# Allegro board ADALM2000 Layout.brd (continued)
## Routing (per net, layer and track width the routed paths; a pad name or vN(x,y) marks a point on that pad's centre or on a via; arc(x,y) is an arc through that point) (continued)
UNNAMED_30_AD9963_I47_TRXD4: length 32.5
  TOP w0.102: v2(63.09,41.09) U2.28
  L6_SIG w0.114: v2(89.63,37.28) 87.22,37.28 86.71,37.79 86.21,37.79 85.82,38.17 85.82,39.95 84.68,41.09 70.33,41.09 68.93,42.49 67.79,42.49 67.03,41.73 63.72,41.73 v2(63.09,41.09)
  BOTTOM w0.102: v2(89.63,37.28) 89.63,37.67 89.32,37.98 R184.1
UNNAMED_30_AD9963_I47_TRXD5: length 36.4
  TOP w0.102: U2.27 62.58,41.96 62.58,40.46 v2(62.08,39.95)
  L6_SIG w0.114: v2(62.08,39.95) 62.08,38.55 61.89,38.36 61.89,37.86 62.2,37.54 63.22,37.54 63.54,37.86 63.54,40.14 64.11,40.71 66.77,40.71 67.79,39.7 68.55,39.7 69.19,40.33 83.41,40.33 84.81,38.94 84.81,38.3 85.7,37.41 86.59,37.41 87.48,36.52 v2(87.86,36.52)
  BOTTOM w0.102: R183.1 v2(87.86,36.52)
UNNAMED_30_AD9963_I47_TRXD6: length 34.3
  TOP w0.102: U2.26 62.09,40.73 v2(62.08,40.71)
  L6_SIG w0.114: v2(62.08,40.71) 62.58,40.21 62.58,39.06 62.71,38.94 63.09,38.94 63.22,39.06 63.22,40.33 62.58,40.97 62.58,41.48 63.09,41.98 66.9,41.98 67.66,42.75 69.06,42.75 70.33,41.48 84.81,41.48 86.71,39.57 86.71,38.94 v2(86.33,38.55)
  BOTTOM w0.102: R182.1 v2(86.33,38.55)
UNNAMED_30_AD9963_I47_TRXD7: length 33.7
  TOP w0.102: v2(61.59,41.22) U2.25
  L6_SIG w0.114: v2(84.3,38.55) 83.79,39.06 83.79,39.44 83.28,39.95 69.44,39.95 68.81,39.32 67.66,39.32 66.65,40.33 64.23,40.33 63.85,39.95 63.85,37.54 63.47,37.16 61.19,37.16 60.55,37.79 60.55,38.11 60.74,38.3 61.31,38.3 61.59,38.57 v2(61.59,41.22)
  BOTTOM w0.102: v2(84.3,38.55) R181.1
UNNAMED_30_AD9963_I47_TRXD8: length 37.7
  TOP w0.102: v2(61.09,40.71) U2.24
  L6_SIG w0.114: v2(61.09,40.71) 61.09,41.5 61.82,42.24 66.77,42.24 67.54,43 70.08,43 71.22,41.86 84.94,41.86 86.98,39.82 86.98,38.16 87.48,37.67 89,37.67 89.13,37.79 89.89,37.79 90.9,36.78 90.9,36.48 v2(91.44,35.95)
  BOTTOM w0.102: R180.1 v2(91.44,35.95)
UNNAMED_30_AD9963_I47_TRXD9: length 36.9
  TOP w0.102: v2(60.59,41.22) U2.23
  L6_SIG w0.114: v2(60.59,41.22) 60.59,41.89 61.19,42.49 66.65,42.49 67.41,43.25 70.2,43.25 71.22,42.24 85.06,42.24 87.35,39.95 87.35,38.3 87.6,38.05 88.87,38.05 89,38.17 90.02,38.17 90.27,37.92 90.78,37.92 v2(91.41,38.55)
  BOTTOM w0.102: R179.1 v2(91.41,38.55)
UNNAMED_30_AD9963_I47_TRXD10: length 34.3
  TOP w0.102: v2(60.09,40.71) U2.22
  L6_SIG w0.114: v2(60.09,40.71) 60.09,41.9 60.93,42.75 66.52,42.75 67.28,43.51 72.49,43.51 73.38,42.62 85.19,42.62 87.86,39.95 v2(87.86,38.55)
  BOTTOM w0.102: R178.1 v2(87.86,38.55)
UNNAMED_30_AD9963_I47_TRXD11: length 35.9
  TOP w0.102: v2(59.59,41.22) U2.21
  L6_SIG w0.114: v2(90.4,38.55) 89.76,38.55 85.32,43 77.57,43 76.93,43.63 73.51,43.63 73.25,43.89 67.28,43.89 66.39,43 60.55,43 59.59,42.04 v2(59.59,41.22)
  BOTTOM w0.102: R177.1 v2(90.4,38.55)
UNNAMED_30_AD9963_I47_TRXIQ: length 34.3
  TOP w0.102: v2(66.59,39.82) 66.59,39.38 66.77,39.19 67.06,39.19 67.2,39.33 67.2,39.68 67.34,39.82 67.54,39.82 67.68,39.68 67.68,39.33 67.83,39.19 68.05,39.19 68.19,39.33 68.19,39.68 68.34,39.82 68.54,39.82 68.68,39.68 68.68,39.33 68.82,39.19 69.44,39.19 69.57,39.06 69.57,38.81 69.44,38.68 66.39,38.68 66.14,38.94 66.14,40.21 66.59,40.65 U2.35
  L6_SIG w0.114: v2(66.59,39.82) 67.48,38.94 68.93,38.94 69.57,39.57 80.57,39.57 80.71,39.43 80.71,39.21 80.86,39.06 81.06,39.06 81.21,39.21 81.21,39.43 81.35,39.57 81.56,39.57 81.7,39.43 81.7,39.21 81.85,39.06 82.05,39.06 82.2,39.21 82.2,39.43 82.34,39.57 83.03,39.57 83.27,39.33 83.27,39.04 83.16,38.94 82.65,38.94 82.27,38.55 v2(81.38,38.55)
  BOTTOM w0.102: v2(81.38,38.55) 81.38,38.24 R176.1
UNNAMED_30_AD9963_I47_TXCLK: length 3.8
  TOP w0.102: U2.37 67.85,42.56 68.76,41.65 70.28,41.65 R174.1
UNNAMED_30_AD9963_I47_TXD0: length 1.6
  TOP w0.102: U2.50 68.27,49.06 68.74,48.59 69.06,48.59
UNNAMED_30_AD9963_I47_TXD1: length 3.5
  TOP w0.102: R172.2 70.46,48.4 70.2,48.14 68.68,48.14 68.26,48.56 U2.49
UNNAMED_30_AD9963_I47_TXD2: length 1.5
  TOP w0.102: U2.48 68.26,48.06 68.62,47.7 69.06,47.7
UNNAMED_30_AD9963_I47_TXD3: length 3.4
  TOP w0.102: U2.47 68.25,47.56 68.62,47.19 70.84,47.19 R169.2
UNNAMED_30_AD9963_I47_TXD4: length 1.5
  TOP w0.102: 69.06,46.68 68.68,46.68 68.3,47.06 U2.46
UNNAMED_30_AD9963_I47_TXD5: length 3.4
  TOP w0.102: U2.45 67.69,46.56 68.3,46.56 68.74,46.11 R167.2
UNNAMED_30_AD9963_I47_TXD6: length 1.6
  TOP w0.102: 69.06,45.54 68.87,45.73 68.62,45.73 68.29,46.06 U2.44
UNNAMED_30_AD9963_I47_TXD7: length 3.5
  TOP w0.102: U2.43 68.22,45.56 68.81,44.97 R113.2
UNNAMED_30_AD9963_I47_TXD8: length 1.7
  TOP w0.102: U2.42 68.27,45.06 68.74,44.59 68.87,44.59 69.06,44.4
UNNAMED_30_AD9963_I47_TXD9: length 3.6
  TOP w0.102: U2.41 68.33,44.56 68.62,44.27 68.62,44.08 68.87,43.83 R109.2
UNNAMED_30_AD9963_I47_TXD10: length 1.7
  TOP w0.102: U2.40 68.25,44.06 69.06,43.25
UNNAMED_30_AD9963_I47_TXD11: length 4.1
  TOP w0.102: R110.2 70.33,42.68 68.74,42.68 68.62,42.81 68.62,43.25 68.31,43.56 U2.39
UNNAMED_30_AD9963_I47_TXIQ: length 2.1
  TOP w0.102: 69.06,42.11 68.68,42.11 68.36,42.43 68.36,42.94 68.24,43.06 U2.38
UNNAMED_30_CAP_I112_N1: length 1
  TOP w0.102: C66.1 70.01,53.48 69.82,53.29
UNNAMED_31_AD8066_I6_INV: length 2.8
  TOP w0.102: C89.1 34.31,50.37 R24.1 34.52,51.46 A3.2
UNNAMED_31_AD8066_I6_NINV: length 8.7
  TOP w0.102: C85.2 31.78,55.06 R22.2 32.08,55.37 36.35,55.37 36.57,55.14 36.57,54.76 36.4,54.58 35.96,54.58 35.79,54.4 A3.3
UNNAMED_31_AD8066_I6_OUT: length 17.2
  TOP w0.102: R26.1 38.79,57.88 38.28,57.88 v2(38.07,58.09) ; C89.2 33.45,50.37 R24.2 33.25,51.46 A3.1 33.25,54.43 33.5,54.68 v2(33.88,54.68)
  BOTTOM w0.102: v2(33.88,54.68) 34.29,55.09 34.29,55.34 34.09,55.55 33.69,55.55 33.04,54.9 33.04,54.12 33.37,53.79 34.64,53.79 35.91,55.06 35.91,56.72 37.08,57.88 37.87,57.88 v2(38.07,58.09)
UNNAMED_31_AD8066_I55_INV: length 2.9
  TOP w0.102: A3.6 35.79,59.81 R25.1 35.59,60.03 C92.1
UNNAMED_31_AD8066_I55_NINV: length 8.7
  TOP w0.102: C88.2 31.77,57.09 R23.2 32.15,55.7 36.8,55.7 37.06,55.95 A3.5
UNNAMED_31_AD8066_I55_OUT: length 17.3
  TOP w0.102: v2(38.07,57.38) 38.25,57.55 38.81,57.55 R27.1 ; v2(33.88,56.21) 34.52,56.84 A3.7 34.52,59.81 R25.2 34.71,60.03 C92.2
  BOTTOM w0.102: v2(38.07,57.38) 37.9,57.55 37.22,57.55 36.24,56.58 36.24,54.93 34.78,53.46 33.24,53.46 32.71,53.99 32.71,55.04 v2(33.88,56.21)
UNNAMED_31_ADA49402V2_I232_: length 4.7
  TOP w0.203: U3.23 44.05,58.1 v1(43.79,58.37)
  BOTTOM w0.102: R34.2 43.1,59.05 v1(43.79,58.37)
  BOTTOM w0.114: C103.2 41.17,59.36 42.08,59.36 R34.2
UNNAMED_31_ADA49402V2_I232__1: length 6.1
  TOP w0.102: R27.2 40.26,57.58 40.56,57.58 R28.2 41.15,57.55 41.43,57.55 v2(41.63,57.35) 41.86,57.58 42.28,57.58 42.95,56.91 42.95,56.54 42.85,56.44 U3.1
  BOTTOM w0.114: C104.1 42.19,57.35 v2(41.63,57.35) 41.07,57.35 R35.1
UNNAMED_31_ADA49402V2_I232__2: length 2.9
  TOP w0.203: v1(41.68,55.94) U3.2
  BOTTOM w0.114: C104.2 42.06,55.94 v1(41.68,55.94) 41.21,55.94 R35.2
UNNAMED_31_ADA49402V2_I232__3: length 6
  TOP w0.102: U3.24 43.14,57.19 42.42,57.91 41.83,57.91 v2(41.63,58.11) 41.4,57.88 41.17,57.88 R29.2 40.59,57.91 40.23,57.91 R26.2
  BOTTOM w0.114: C103.1 40.94,58.11 v2(41.63,58.11) 42.31,58.11 R34.1
UNNAMED_31_ADA49402V2_I232__4: length 7.7
  TOP w0.102: U3.19 46.47,57.19 46.86,57.58 49.2,57.58 52.31,54.46
UNNAMED_31_ADA49402V2_I232__5: length 7.7
  TOP w0.102: U3.18 46.73,56.44 46.58,56.59 46.58,56.83 47,57.25 49.06,57.25 51.61,54.7 51.61,54.23 51.69,54.15 R38.1
UNNAMED_31_ADA49402V2_I232_VOCM: length 9.3
  TOP w0.203: U3.17 47.59,55.94 v1(47.85,56.21) ; v1(45.82,51.51) 45.82,52.02 45.55,52.28 U3.11
  BOTTOM w0.203: R36.1 47.85,56.92 v1(47.85,56.21) 46.33,54.68 46.33,53.92 45.82,53.41 v1(45.82,51.51)
UNNAMED_31_ADA49402V2_I233_: length 1.9
  TOP w0.203: U3.8 44.05,52.41 v1(43.91,52.27)
  BOTTOM w0.203: v1(43.91,52.27) 44.22,51.97 R33.2
UNNAMED_31_ADA49402V2_I233__1: length 7
  TOP w0.203: v1(47.72,53.29) 47.7,53.31 46.94,53.31 46.8,53.45 U3.13
  BOTTOM w0.203: R39.1 50.9,55.5 50.57,55.83 49.12,55.83 48.23,54.94 48.23,53.79 v1(47.72,53.29)
UNNAMED_31_ADA49402V2_I233__2: length 7.8
  TOP w0.203: U3.12 46.05,52.54 46.2,52.4 46.45,52.4 v1(46.71,52.65)
  BOTTOM w0.203: R40.1 50.6,55.09 50.37,55.32 49.25,55.32 48.74,54.81 48.74,53.29 48.11,52.65 v1(46.71,52.65)
UNNAMED_31_ADA49402V2_I233__3: length 1.8
  TOP w0.203: v1(41.88,54.3) 42.02,54.44 U3.5
  BOTTOM w0.102: R32.2 41.17,54.3 v1(41.88,54.3)
UNNAMED_31_ADA49402V2_I233__4: length 2.8
  TOP w0.203: U3.7 43.55,52.67 v1(43.15,52.27)
  BOTTOM w0.102: R31.2 R33.1
  BOTTOM w0.203: v1(43.15,52.27) 43.15,51.71 R33.1
UNNAMED_31_ADA49402V2_I233__5: length 2.7
  TOP w0.203: v1(41.88,53.54) 42.28,53.94 U3.6
  BOTTOM w0.102: R30.2 42.6,53.54 v1(41.88,53.54) 41.17,53.54 R32.1
UNNAMED_31_ADG202N_I1_D: length 17.7
  TOP w0.102: A4.15 25.91,59.51 26.03,59.64 29.03,59.64 29.16,59.51 A4.10 29.16,57.02 28.9,56.77 28.9,55.98 29.16,55.73 29.87,55.73 v2(30.07,55.93) 30.25,55.75 30.58,55.75 R23.1 30.91,57.09 C88.1
  BOTTOM w0.102: A2.6 30.16,53.53 30.02,53.67 29.63,53.67 29.45,53.85 29.45,54.04 29.59,54.18 30.79,54.18 31.23,54.61 31.23,55.52 30.82,55.93 v2(30.07,55.93)
UNNAMED_31_ADG202N_I1_S: length 13.7
  TOP w0.203: A4.14 26.56,57.39 26.39,57.22 24.99,57.22 24.74,57.48 24.74,58.37 v1(24.23,58.87)
  BOTTOM w0.102: C185.1 C181.2 21.57,57.35 20.93,57.35 20.51,56.93 R17.2 19.12,56.93 C73.2 ; C185.1 22.54,57.89 R18.1 22.54,60.3 C74.1 ; C185.1 23.09,57.86 23.21,57.86 v1(24.23,58.87)
UNNAMED_31_ADG202N_I2_S: length 17.7
  TOP w0.102: C72.2 19.72,56.72 R16.2 20.71,55.73 21.33,55.73 v2(21.56,55.95) 22.11,55.95 C69.1 23.51,55.75 28.01,55.75 28.24,55.98 28.24,57.11 28.51,57.37 A4.11
  BOTTOM w0.102: v2(21.56,55.95) 21.82,56.21 C181.1 21.68,56.46 21.31,56.46 20.58,55.73 R17.1 19.12,55.73 C73.1
UNNAMED_31_ADG202N_I19_D: length 17.6
  TOP w0.102: A4.2 25.91,51.64 26.01,51.53 29.06,51.53 29.16,51.64 A4.7 29.16,53.8 28.9,54.05 28.9,55.12 29.18,55.39 29.89,55.39 v2(30.07,55.22) 30.27,55.42 30.56,55.42 R22.1 30.9,55.06 C85.1
  BOTTOM w0.102: v2(30.07,55.22) 30.26,55.41 30.26,55.53 30.33,55.6 30.68,55.6 30.9,55.38 30.9,54.75 30.66,54.51 29.45,54.51 29.12,54.18 29.12,53.78 29.01,53.67 28.34,53.67 28.21,53.53 A2.3
UNNAMED_31_ADG202N_I19_S: length 17.6
  TOP w0.102: C75.2 19.72,54.43 R19.2 20.69,55.39 21.36,55.39 v2(21.56,55.19) 22.11,55.19 C71.1 23.53,55.42 27.3,55.42 27.66,55.06 27.66,54.68 27.4,54.43 26.9,54.43 26.56,54.09 A4.3
  BOTTOM w0.102: C76.1 20.32,54.37 R20.1 20.64,54.05 21.25,54.05 21.75,54.55 C189.1 21.56,54.8 v2(21.56,55.19)
UNNAMED_31_ADG202N_I20_S: length 16.4
  TOP w0.203: v1(28.17,54.94) 28.51,54.6 A4.6
  BOTTOM w0.102: C77.1 23.4,52.05 R21.1 23.31,53.08 C336.1 ; C336.1 C189.2 21.06,53.55 20.58,53.07 R20.2 19.12,53.07 C76.2 ; C336.1 22.84,53.55 23.47,54.18 23.47,54.94 24.1,55.57 27.53,55.57 v1(28.17,54.94)
UNNAMED_31_ADG1404V2_I235_D: length 12
  BOTTOM w0.102: A2.2 27.56,50.97 28.04,50.49 31.98,50.49 32.61,51.13 34.14,51.13 35.28,52.27 36.17,52.27 36.35,52.09 U8.6
UNNAMED_31_DIO3PV3_I80_N: length 4.8
  BOTTOM w0.203: R40.2 51.2,54.05 D21.2 52.48,52.77 52.67,52.77 54.07,54.18 54.07,54.41 D20.2
UNNAMED_31_DIO3PV3_I80_P: length 6.2
  L5_SIG w0.114: v1(50.74,52.99) 50.74,53.63 v1(52.55,55.45)
  BOTTOM w0.203: D21.1 51.27,52.46 v1(50.74,52.99) ; D20.1 52.77,54.08 R39.2 51.99,54.89 v1(52.55,55.45)
UNNAMED_32_AD8066_I42_INV: length 2.9
  TOP w0.102: A5.6 35.79,47.87 R50.1 35.59,48.09 C146.1
UNNAMED_32_AD8066_I42_NINV: length 8.7
  TOP w0.102: A5.5 37.06,44.02 36.78,43.74 32.18,43.74 R48.2 31.77,45.15 C143.2
UNNAMED_32_AD8066_I42_OUT: length 16.9
  TOP w0.102: v2(38.34,45.44) 38.54,45.64 38.79,45.64 R53.1 ; C146.2 34.71,48.09 R50.2 34.52,47.87 A5.7 34.52,44.9 v2(33.88,44.27)
  BOTTOM w0.102: v2(33.88,44.27) 33.48,43.87 32.71,43.1 32.71,42.05 33.24,41.53 34.78,41.53 37.56,44.31 37.56,45.29 37.89,45.62 38.16,45.62 v2(38.34,45.44)
UNNAMED_32_AD8066_I82_INV: length 2.9
  TOP w0.102: C147.1 34.31,38.31 R51.1 34.52,39.39 34.52,41.09
UNNAMED_32_AD8066_I82_NINV: length 8.8
  TOP w0.102: C145.2 31.78,43.12 R49.2 32.05,43.41 36.37,43.41 36.65,43.13 36.65,42.9 36.4,42.64 35.96,42.64 35.79,42.47 35.79,41.09
UNNAMED_32_AD8066_I82_OUT: length 16.9
  TOP w0.102: v2(33.88,42.75) 33.45,42.75 33.25,42.54 33.25,39.39 R51.2 33.45,38.31 C147.2 ; v2(38.34,46.15) 38.52,45.97 38.81,45.97 R52.1
  BOTTOM w0.102: v2(38.34,46.15) 38.14,45.95 37.76,45.95 37.23,45.42 37.23,44.45 34.64,41.86 33.37,41.86 33.04,42.19 33.04,42.96 33.62,43.54 33.71,43.63 34.01,43.63 34.21,43.43 34.21,43.08 v2(33.88,42.75)
UNNAMED_32_ADA49402V2_I190_: length 3
  TOP w0.203: v2(41.63,44.01) 41.63,44 U4.2
  BOTTOM w0.114: C163.2 42.06,44.01 v2(41.63,44.01) 41.21,44.01 R61.2
UNNAMED_32_ADA49402V2_I190__1: length 6
  TOP w0.102: R52.2 40.26,45.95 40.56,45.95 R55.2 41.17,45.95 41.43,45.95 v2(41.63,46.15) 41.83,45.95 42.48,45.95 43.17,45.25 U4.24
  BOTTOM w0.114: C162.1 40.94,46.17 41.58,46.17 41.6,46.15 v2(41.63,46.15) 41.65,46.15 41.68,46.17 42.31,46.17 R60.1
UNNAMED_32_ADA49402V2_I190__2: length 6
  TOP w0.102: U4.1 42.95,44.65 42.95,45.01 42.34,45.62 41.81,45.62 v2(41.63,45.44) 41.45,45.62 41.15,45.62 R54.2 40.59,45.62 40.23,45.62 R53.2
  BOTTOM w0.114: R61.1 41.07,45.41 41.6,45.41 v2(41.63,45.44) 41.65,45.41 42.19,45.41 C163.1
UNNAMED_32_ADA49402V2_I190__3: length 4.9
  TOP w0.203: U4.23 44.05,46.04 43.79,46.3 43.41,46.3 43.15,46.56 v1(43.15,47.06)
  BOTTOM w0.102: R60.2 42.47,47.11 42.52,47.06 v1(43.15,47.06)
  BOTTOM w0.114: R60.2 42.11,47.39 41.14,47.39 C162.2
UNNAMED_32_ADA49402V2_I190__4: length 3.6
  TOP w0.102: R63.1 49.15,45.87 49.03,45.87 47.05,45.87 46.44,45.25 U4.19
UNNAMED_32_ADA49402V2_I190__5: length 3.6
  TOP w0.102: R64.1 49.27,45.16 48.89,45.54 47.19,45.54 46.68,45.03 46.68,44.62 U4.18
UNNAMED_32_ADA49402V2_I190_VOCM: length 9.8
  TOP w0.203: v1(45.69,40.33) 45.55,40.47 U4.11 ; U4.17 47.46,44 v1(47.72,44.27)
  L5_SIG w0.114: v1(47.72,44.27) 47.72,41.22 47.98,40.97 47.98,40.08 47.6,39.7 46.33,39.7 v1(45.69,40.33)
  BOTTOM w0.102: R62.1 47.72,43.59 v1(47.72,44.27)
UNNAMED_32_ADA49402V2_I191_: length 1.8
  TOP w0.203: U4.8 44.05,40.47 v1(43.91,40.33)
  BOTTOM w0.203: R59.2 43.91,39.62 v1(43.91,40.33)
UNNAMED_32_ADA49402V2_I191__1: length 7.4
  TOP w0.203: v1(46.45,40.33) 46.05,40.73 U4.12
  BOTTOM w0.203: R66.1 47.72,45.1 47.22,44.59 47.22,41.09 v1(46.45,40.33)
UNNAMED_32_ADA49402V2_I191__2: length 6.4
  TOP w0.203: v1(46.71,41.47) 46.71,41.91 U4.13
  BOTTOM w0.203: R65.1 48.11,46.11 46.71,44.71 v1(46.71,41.47)
UNNAMED_32_ADA49402V2_I191__3: length 1.8
  TOP w0.203: v1(41.88,42.36) 42.02,42.5 U4.5
  BOTTOM w0.102: R58.2 42.6,42.36 v1(41.88,42.36)
UNNAMED_32_ADA49402V2_I191__4: length 2.8
  TOP w0.203: U4.7 43.55,40.73 v1(43.15,40.33)
  BOTTOM w0.102: R57.2 R59.1
  BOTTOM w0.203: R59.1 43.15,39.62 v1(43.15,40.33)
UNNAMED_32_ADA49402V2_I191__5: length 2.7
  TOP w0.203: U4.6 42.28,42 v1(41.88,41.6)
  BOTTOM w0.102: R56.2 41.17,41.6 v1(41.88,41.6) 42.6,41.6 R58.1
UNNAMED_32_ADG202N_I18_S: length 12.5
  TOP w0.102: A1.14 26.56,45.58 26.39,45.41 24.99,45.41 23.98,46.43 v1(23.47,46.68)
  BOTTOM w0.102: C130.2 19.25,45.5 R45.2 20.64,45.5 21.18,46.05 21.18,46.59 21.21,46.62 ; C134.1 21.21,46.62 ; 21.21,46.62 R46.1 21.4,46.72 21.82,46.3 22.21,46.3 C340.1 ; v1(23.47,46.68) 23.09,46.3 22.7,46.3 C340.1 ; C339.2 C340.1
UNNAMED_32_ADG202N_I25_S: length 17.1
  TOP w0.102: C132.2 19.72,44.78 R44.2 20.71,43.79 21.36,43.79 v2(21.56,43.99) 22.08,43.99 C128.1 23.51,43.81 27.94,43.81 28.51,44.38 A1.11
  BOTTOM w0.102: C130.1 19.25,44.3 R45.1 20.86,43.99 v2(21.56,43.99) 22.29,43.99 C339.1
UNNAMED_32_ADG202N_I26_S: length 15.2
  TOP w0.203: v1(28.67,41.98) 28.51,41.82 A1.6
  BOTTOM w0.102: C338.1 23.21,41.21 23.56,41.57 25.54,41.57 25.88,41.22 27.91,41.22 v1(28.67,41.98) ; C338.1 22.21,40.97 21.94,40.97 21.27,40.3 R43.1 21.08,40.4 19.85,40.4 ; C338.1 C337.2 ; 19.85,40.4 C131.1 ; 19.85,40.4 20.17,40.71 20.17,41.48 20.45,41.76 ; 20.45,41.76 R42.2 ; 20.45,41.76 19.25,41.76 C95.2
UNNAMED_32_ADG202N_I34_S: length 17.1
  TOP w0.102: C129.2 19.98,41.48 R41.2 20.69,43.46 21.39,43.46 v2(21.56,43.28) 22.08,43.28 C126.1 22.74,42.66 23.57,43.48 27.43,43.48 27.63,43.28 27.63,42.8 27.33,42.49 27,42.49 26.56,42.05 A1.3
  BOTTOM w0.102: C337.1 22.29,43.28 v2(21.56,43.28) 20.86,43.28 R42.1 19.25,42.96 C95.1
UNNAMED_32_ADG202N_I163_S: length 15.6
  TOP w0.102: A1.2 25.91,39.7 26.03,39.57 29.03,39.57 29.16,39.7 A1.7 29.16,43.25 29.36,43.46 29.89,43.46 v2(30.07,43.28) 30.25,43.46 30.58,43.46 R49.1 30.9,43.12 C145.1
  BOTTOM w0.102: A2.14 28.21,45.63 28.73,45.11 28.73,44.02 29.28,43.46 29.89,43.46 v2(30.07,43.28)
UNNAMED_32_ADG202N_I164_S: length 15.7
  TOP w0.102: A1.15 25.91,47.57 26.03,47.7 29.03,47.7 29.16,47.57 A1.10 29.16,44.04 29.41,43.79 29.87,43.79 v2(30.07,43.99) 30.27,43.79 30.56,43.79 R48.1 30.91,45.15 C143.1
  BOTTOM w0.102: v2(30.07,43.99) 29.87,43.79 29.42,43.79 29.06,44.15 29.06,45.11 29.36,45.41 29.94,45.41 30.16,45.63 A2.11
UNNAMED_32_ADG1404V2_I201_D: length 10.1
  BOTTOM w0.102: A2.10 30.81,45.57 31.47,44.9 31.47,42.36 33.37,40.46 35.28,40.46 35.46,40.28 U9.6
UNNAMED_32_DIO3PV3_I76_N: length 5.8
  L5_SIG w0.203: v1(49.88,47.25) 49.62,46.98 v1(49.62,44.27)
  BOTTOM w0.203: v1(49.62,44.27) R66.2 50.51,45.1 D23.2 ; D22.2 v1(49.88,47.25)
UNNAMED_32_DIO3PV3_I76_P: length 4.6
  BOTTOM w0.203: R65.2 50.51,46.11 D22.1 51.21,46.25 51.35,46.1 51.35,44.09 51.23,43.96 D23.1
UNNAMED_33_AD8000_I139_FB: length 2.8
  TOP w0.102: A7.2 29.64,27.76 R107.2 30.45,26.06 R194.2
UNNAMED_33_AD8000_I139_INV: length 7.1
  TOP w0.305: R102.2 R101.2 32.23,25.78 32.23,27.63 32.05,27.82 C266.1 31.46,27.81 R107.1 30,28.26 A7.3
UNNAMED_33_AD8000_I139_NINV: length 7
  TOP w0.203: v1(31.21,30.93) 30.9,30.62 C260.1 30.9,29.32 R105.1 30.35,28.76 A7.4
  BOTTOM w0.102: v1(31.21,30.93) 31.53,31.25 31.79,31.25 32.96,32.42 R99.2
UNNAMED_33_AD8000_I139_OUT: length 2.6
  TOP w0.305: R132.1 24.92,27.76 A7.7
UNNAMED_33_AD8000_I141_FB: length 2.5
  TOP w0.102: A9.2 29.56,33.61 30.25,32.92 R108.2 30.33,32.16 R193.2
UNNAMED_33_AD8000_I141_INV: length 6
  TOP w0.305: R104.2 34.8,33.78 R103.2 34,33.79 C267.1 30.33,33.79 R108.1 30.15,33.78 29.82,34.11 A9.3
UNNAMED_33_AD8000_I141_NINV: length 5.3
  TOP w0.203: A9.4 29.68,34.61 29.92,34.84 R106.1 32.08,34.84 C261.1 33.86,34.69 R100.2
UNNAMED_33_AD8000_I141_OUT: length 2.5
  TOP w0.305: A9.7 24.48,33.61 R133.1
UNNAMED_33_ADOPAMP2_I1_OUT: length 6.4
  TOP w0.305: C252.2 35.69,23.22 R95.2 ; R102.1 33.93,24.28 34.39,23.82 35.44,23.82 R95.2 ; R95.2 35.53,24.24 A10.1
UNNAMED_33_ADOPAMP2_I101_OUT: length 5.1
  TOP w0.305: R104.1 36.78,33.73 36.8,33.75 ; 36.8,33.75 36.8,34.33 R96.2 36.96,35.67 C255.2 ; 36.8,33.75 A10.7
UNNAMED_33_CAP_I33_N1: length 1.8
  TOP w0.102: R101.1 R97.2 32.87,23.37 C256.1
UNNAMED_33_CAP_I95_N1: length 1.8
  TOP w0.203: R98.2 32.24,33.02 C257.1 33.9,33.02 R103.1
UNNAMED_33_CAP_I123_N2: length 0.9
  TOP w0.102: R193.1 31.34,32.16 C267.2
UNNAMED_33_CAP_I124_N2: length 1
  TOP w0.102: C266.2 31.47,26.06 R194.1
UNNAMED_34_AD56X5_I239_ADDR1: length 4.7
  BOTTOM w0.102: U11.2 38.23,29.63 39.01,28.85 R119.2 R120.1
UNNAMED_34_AD56X5_I239_CLRN: length 19.5
  BOTTOM w0.102: R144.2 35.33,28.44 35.87,28.98 U11.1 37.48,28.98 37.56,28.9 37.56,27.12 37.82,26.87 41.12,26.87 41.37,27.12 41.37,28.14 40.77,28.75 40.77,32.08 ; U11.9 41.66,32.23 41.5,32.08 40.77,32.08 ; 40.77,32.08 38.2,32.08 38.04,32.23 U11.6
UNNAMED_34_AD56X7_I238_ADDR: length 3.1
  TOP w0.102: v1(25.82,19.63) 25.8,19.65 U20.6
  BOTTOM w0.102: v1(25.82,19.63) 25.82,18.63 R140.2 R141.1
UNNAMED_34_AD56X7_I238_CLRN: length 4.1
  TOP w0.102: 21.3,19.65 21.3,20.02 21.17,20.15 U20.4 ; 21.3,19.65 U20.5 ; 21.3,19.65 21.83,19.12 R142.2
UNNAMED_34_AD56X7_I238_VOUTA: length 2.5
  TOP w0.203: R150.1 21.69,22.17 21.17,21.65 U20.1
UNNAMED_34_AD56X7_I238_VOUTB: length 3.4
  TOP w0.203: R151.1 22.58,22.43 21.3,21.15 U20.2
UNNAMED_34_AD8657V2_I252_: length 3.5
  TOP w0.102: R123.2 50.39,31.22 C304.1 50.38,30.22 R127.1 49.46,30.18 A6.2
UNNAMED_34_AD8657V2_I253_: length 3.4
  TOP w0.203: 43.53,34.93 43.53,34.94 R121.2 43.61,35.63 44.42,35.63 44.55,35.76 A8.6 ; 43.53,34.93 C302.1 ; 43.53,34.93 R125.1
UNNAMED_34_AD8657V2_I254_: length 3.4
  TOP w0.102: R122.2 50.95,35.89 50.84,35.89 C303.1 49.51,35.44 R126.1 49.33,35.26 A8.2
UNNAMED_34_AD8657V2_I255_: length 3.3
  TOP w0.102: R124.2 C305.1 43.91,30.61 R128.1
  TOP w0.203: A6.6 43.99,30.68 R128.1
UNNAMED_34_AD8657V2_I284_: length 3.9
  TOP w0.305: v1(51.47,28.27) 51.67,28.07 A11.6
  BOTTOM w0.305: v1(51.47,28.27) 51.47,28.87 R117.2 ; v1(51.47,28.27) 50.8,28.27 R118.1 ; v1(51.47,28.27) 52.04,28.27 C94.1
UNNAMED_34_AD8657V2_I284__1: length 3.8
  TOP w0.305: R115.2 R116.1 53.93,30.11 C56.1 52.33,29.63 A11.5
UNNAMED_34_AD8657V2_I284_OUT: length 3.5
  TOP w0.305: R143.1 50.76,27.57 v1(51.47,27.57) 51.48,27.57 A11.7
  BOTTOM w0.305: R118.2 50.86,27.57 v1(51.47,27.57) 51.86,27.57 C94.2
UNNAMED_35_AD8657V2_I160_: length 3
  TOP w0.102: A11.2 56.04,27.57 56.11,27.51 56.11,26.55 56.28,26.38 R139.2 R136.1
UNNAMED_35_ADA48051_I114_: length 5.7
  TOP w0.406: R159.2 R160.1 15.01,7.83 C200.1 15.02,7.12 14.83,6.93 14.83,5.53 15.1,5.27 A14.4
UNNAMED_35_ADA48051_I114_VOUT: length 7
  TOP w0.406: R163.1 12.72,6.57 A14.1 14.14,7.82 C200.2
  TOP w0.457: D26.A 8.96,6.35 C179.1 10.96,6.68 11.97,6.68 R163.1
UNNAMED_35_ADA48051_I125_: length 5.7
  TOP w0.406: A12.4 15.1,10.98 14.83,11.25 14.83,12.65 15.02,12.83 C201.1 15.01,13.54 R161.1 R158.2
UNNAMED_35_ADA48051_I125_VOUT: length 7.7
  TOP w0.406: R162.1 12.74,12.65 13.94,12.65 14.14,12.45 ; A12.1 14.14,12.45 ; 14.14,12.45 14.14,13.53 C201.2
  TOP w0.457: D1.C 8.96,11.94 C175.1 10.64,12.65 11.09,13.09 R162.1
UNNAMED_35_CAP_I76_N2: length 1.1
  BOTTOM w0.305: C306.2 53.88,28.39 C307.1
UNNAMED_36_ADF43609_I40_CC: length 1.3
  TOP w0.203: C227.1 64.13,62.73 U14.12
UNNAMED_36_ADF43609_I40_CN: length 2.3
  TOP w0.203: U14.14 v1(62.46,60.26)
  BOTTOM w0.305: v1(62.46,60.26) 62.46,61.35 C230.1
UNNAMED_36_ADF43609_I40_L1: length 4.8
  TOP w0.102: L13.2 65.86,65.58 65.5,65.22 65.5,64.77 R83.2 65.5,63.95 65.5,62.03 65.63,61.9 U14.9
UNNAMED_36_ADF43609_I40_L2: length 4.8
  TOP w0.102: U14.10 65.13,61.9 65.25,62.02 65.25,63.96 R84.2 65.25,64.77 65.25,65.22 64.9,65.58 L14.2
UNNAMED_36_ADF43609_I40_RFOUTA: length 4.7
  TOP w0.102: C236.1 71.38,59.88 70.65,59.88 L15.1 70.05,59.84 68.02,59.84 67.94,59.76 U14.4
UNNAMED_36_ADF43609_I40_RFOUTB: length 4.7
  TOP w0.102: U14.5 67.93,60.26 68.02,60.17 70.03,60.17 L16.1 70.6,60.21 71.43,60.21 C237.1
UNNAMED_36_ADF43609_I40_RSET: length 2.2
  TOP w0.203: R85.2 63.38,62.22 U14.13
UNNAMED_36_CAP_I47_N1: length 1.7
  TOP w0.305: Y1.3 60.49,61.79 C52.1
UNNAMED_36_CAP_I53_N1: length 1
  TOP w0.305: C238.1 72,65.53 R6.2
UNNAMED_37_ADP237X_I231_FB: length 3.4
  TOP w0.102: v2(35.53,11.25) 35.75,11.47 U7.5
  BOTTOM w0.203: R70.1 v2(35.53,11.25) 34.57,11.25 C184.1 34.45,12.26 R72.1
UNNAMED_37_ADP237X_I231_SW: length 1.1
  TOP w0.305: U7.7 37.05,10.36
UNNAMED_37_ADP1614_I262_CLRES: length 2.4
  TOP w0.102: U12.9 46.45,6.93 v2(46.58,6.68)
  BOTTOM w0.203: R12.1 46.58,7.39 v2(46.58,6.68) 46.58,5.96 R11.2
UNNAMED_37_ADP1614_I262_COMP: length 3.2
  TOP w0.102: C15.1 47.98,12.21 C17.1 47.91,11.05 47.32,10.46 U12.1
UNNAMED_37_ADP1614_I262_FB: length 2.8
  TOP w0.102: U12.2 46.45,10.99 v2(46.84,11.38)
  BOTTOM w0.203: R73.1 R69.1 47.55,11.38 v2(46.84,11.38)
UNNAMED_37_ADP1614_I262_SS: length 2
  TOP w0.102: U12.10 46.99,7.5 47.53,7.5 v2(47.85,7.19)
  BOTTOM w0.203: v2(47.85,7.19) 47.85,8.01 47.92,8.07
UNNAMED_37_ADP1614_I262_SW1: length 3.8
  TOP w0.305: 44.57,7.46 U12.6 ; U12.6 U12.7 45.45,6.8 ; U12.6 44.95,6.8
  TOP w0.889: 41.73,7.2 D25.A 40.87,6.49
UNNAMED_37_ADP1614_I262_VIN: length 3.4
  TOP w0.254: U12.8 v2(45.95,6.68) 45.95,5.97 C16.1
  TOP w0.508: C16.1 45.82,5.85 R68.1
  BOTTOM w0.203: R11.1 45.95,6.09 v2(45.95,6.68)
UNNAMED_37_CAP_I212_N1: length 14.8
  TOP w0.508: 30.17,17.12 E8.1 ; E8.1 30.72,17.73 ; E8.1 30.17,18.34
  TOP w1.016: 31.01,16.46 C192.1 ; C192.1 31.91,15.4 ; C192.1 31.91,17.51 ; 31.91,17.94 C191.1 31.01,19
  BOTTOM w0.203: R71.2 32.56,14.09 32.23,14.42 v1(32.23,15.06)
  BOTTOM w1.016: 31.91,15.4 C192.1 ; C192.1 31.01,16.46 ; C192.1 31.91,17.51 ; 31.91,17.94 C191.1 ; C191.1 31.91,20.05 ; C191.1 31.01,19
  vias: v1(30.71,19.63) v1(30.71,18.87) v1(30.71,16.58) v1(30.71,15.82) v1(30.71,15.06) v1(31.09,17.73) v1(31.47,15.06) v1(31.72,17.73) v1(32.36,17.73)
UNNAMED_37_CAP_I222_N1: length 2.9
  BOTTOM w0.203: C188.1 33.57,10.37 C184.2 33.58,11.38 R72.2 33.58,13.15 R71.1
UNNAMED_37_CAP_I222_N2: length 2.7
  TOP w1.016: 32.7,11.69 C186.1 33.75,10.79
  BOTTOM w0.203: C188.2 v1(32.23,10.36)
UNNAMED_37_CAP_I260_N2: length 0.9
  TOP w0.102: R67.1 47.97,13.08 C15.2
UNNAMED_37_CAP_I315_N1: length 3.1
  TOP w0.635: 43.09,10.96 C23.1 42.12,10.4
  TOP w0.889: 40.87,11.19 D25.C 41.73,10.47
UNNAMED_37_LINLT1761_I320_ADJ: length 3.1
  TOP w0.254: U17.4 v1(30.96,65.16)
  BOTTOM w0.203: v1(30.96,65.16) 31.56,65.16 R165.1 31.66,65.06 R164.2
UNNAMED_38_ADP2114_I358_FREQ: length 2
  TOP w0.305: R743.2 96.35,55.92 U518.3
UNNAMED_38_ADP2114_I358_OPCFG: length 2.1
  TOP w0.305: v2(94.97,55.06) 94.97,54.94 94.85,54.82 U518.6
  BOTTOM w0.102: R747.1 95.22,54.61 95.22,54.68 94.97,54.94 v2(94.97,55.06)
UNNAMED_38_ADP2114_I358_SS1: length 3.4
  TOP w0.203: U518.30 99.54,52.26 v2(99.92,52.52)
  BOTTOM w0.203: C745.2 v2(99.92,52.52)
UNNAMED_38_ADP2114_I358_SS2: length 3.9
  TOP w0.203: U518.11 91.48,52.26 v2(91.29,52.4)
  BOTTOM w0.203: v2(91.29,52.4) 91.41,52.27 92.3,52.27 92.56,52.02 92.56,51.71 C746.2
UNNAMED_38_ADP2114_I358_SW1: length 3
  TOP w0.305: U518.24 U518.23 96.85,48.1 97,47.95 ; U518.24 97.44,48.97 97.64,48.97 97.89,48.71 ; U518.24 97.35,48.36
UNNAMED_38_ADP2114_I358_SW3: length 3
  TOP w0.305: 93.85,48.36 U518.17 ; U518.17 93.76,48.97 93.57,48.97 93.32,48.71 ; U518.17 U518.18 94.35,48.1 94.21,47.95
UNNAMED_38_ADP2114_I447_FREQ: length 1.9
  TOP w0.203: R74.2 81.62,58.08 U6.3
UNNAMED_38_ADP2114_I447_OPCFG: length 2
  TOP w0.203: U6.6 80.12,57.82 R75.2
UNNAMED_38_ADP2114_I447_SS1: length 2.2
  TOP w0.203: 84.55,55.19 83.91,54.54 U6.30
  TOP w0.254: C193.2 84.55,55.19
UNNAMED_38_ADP2114_I447_SS2: length 1.8
  TOP w0.254: C194.2 77.32,54.94 77.71,54.54 U6.11
UNNAMED_38_ADP2114_I447_SW1: length 2.8
  TOP w0.305: 82.62,50.65 U6.24 ; U6.24 82.71,51.25 82.9,51.25 83.28,50.87 ; U6.24 U6.23 82.12,50.65
UNNAMED_38_ADP2114_I447_SW3: length 2.6
  TOP w0.305: U6.17 79.03,51.25 78.84,51.25 78.59,51 ; U6.17 U6.18 79.62,50.65 ; U6.17 79.12,50.65
UNNAMED_38_ADP2114_I447_V1SET: length 4.1
  TOP w0.203: v1(84.55,56.21) 84.05,55.7 84.05,55.19 83.9,55.04 U6.31
  TOP w0.254: v1(84.55,56.21) 85.27,56.21 R91.1
  BOTTOM w0.203: v1(84.55,56.21) 85.06,55.7 85.06,55.4 R92.1
UNNAMED_38_ADP2114_I447_V2SET: length 3.2
  TOP w0.254: R203.1 76.55,56.79 76.55,56.13 R149.1 76.86,55.83 77.19,55.83 77.97,55.04 U6.10
UNNAMED_38_CAP_I366_N2: length 0.9
  BOTTOM w0.102: C757.2 92.56,55.13 R760.2
UNNAMED_38_CAP_I379_N1: length 8.3
  BOTTOM w0.203: C762.1 99.22,44.14 98.65,44.14 98.52,44.27 98.52,44.98 R765.2
  BOTTOM w0.762: 99.79,42.67 C762.1 100.85,43.57 ; 100.24,41.22 E768.1 101.07,40.33 ; 101.15,43.57 C761.1 102.21,42.67
  vias: v1(99.67,42.11) v1(99.67,41.48) v1(100.3,42.11) v1(100.3,41.48) v1(100.94,42.11) v1(100.94,41.48) v1(101.57,42.11) v1(101.57,41.48)
UNNAMED_38_CAP_I387_N2: length 1
  BOTTOM w0.203: R752.2 99.36,54.94 C753.2
UNNAMED_38_CAP_I457_N1: length 5.3
  BOTTOM w0.203: E21.1 76.3,47.46 R205.1
  BOTTOM w0.635: 75.07,46.62 C215.1 74.01,45.72 ; 76.3,45.67 E21.1 75.47,46.56
  vias: v1(74.65,45.41) v1(74.65,44.78) v1(74.65,44.14) v1(75.28,46.68) v1(75.28,46.05) v1(75.28,45.41) v1(75.28,44.78) v1(75.28,44.14) v1(75.92,44.52)
UNNAMED_38_CAP_I463_N1: length 1.2
  BOTTOM w0.203: R90.2 81.51,57.81 C207.1
UNNAMED_38_CAP_I465_N2: length 1.6
  BOTTOM w0.203: R204.1 80.11,56.76 80.11,58.04 C203.2
UNNAMED_39_ICUSB3320C_I29_RBIAS: length 1.6
  TOP w0.102: v1(59.73,29.72) 60.13,30.12 U524.24
  BOTTOM w0.406: v1(59.73,29.72) 60.4,29.72 R800.1
UNNAMED_39_ICUSB3320C_I29_REFCL: length 1.3
  TOP w0.254: U524.26 61.33,28.62 R797.1
UNNAMED_39_RES_I67_N2: length 1.3
  TOP w0.356: Y523.3 60.38,27.42 R797.2
UNNAMED_40_ICXC7Z010_I16_PSCLK5: length 6.8
  TOP w0.102: R581.2 78.08,19.43 78.08,19.71 80.9,22.53 U511.C7
UNNAMED_40_ICXC7Z010_I16_PSMIO7: length 5.3
  TOP w0.102: U511.D9 v2(79.76,24.79)
  BOTTOM w0.102: R584.2 77.24,21.84 78.78,23.38 78.78,24.39 79.17,24.79 v2(79.76,24.79)
UNNAMED_40_ICXC7Z010_I16_PSMIO8: length 9
  TOP w0.102: R592.1 77.05,15.17 77.05,16.43 80.01,19.4 80.01,20.51 80.89,21.39 80.89,21.96 U511.B6
UNNAMED_40_RES_I48_N1: length 2.4
  TOP w0.102: Y578.3 74.35,15.71 R581.1
UNNAMED_41_CAP_I89_N1: length 2.8
  TOP w0.203: v2(102.78,30.74) 102.46,31.06 102.2,31.06 U509.5
  BOTTOM w0.102: R642.2 102.51,29.4 C644.1 102.78,30.24 v2(102.78,30.74)
UNNAMED_41_ICMT41K256M16_I99_ZQ: length 4.1
  TOP w0.102: v2(93.57,18.21) 95.63,16.16 U646.L8
  BOTTOM w0.165: R661.1 93.23,17.87 v2(93.57,18.21)
UNNAMED_41_ICTPS51206_I44_S3: length 1.8
  TOP w0.102: v1(99.41,32.78) 99.92,32.78 100.26,32.43
  BOTTOM w0.102: v1(99.41,32.78) 99.41,32.4 99.59,32.22 R640.2
UNNAMED_41_ICTPS51206_I44_S5: length 1.4
  TOP w0.102: R638.2 98.7,32.86 U509.9
UNNAMED_41_ICTPS51206_I44_VLDOI: length 1.6
  TOP w0.203: 101.11,30.45 101.8,29.76 R653.2
UNNAMED_41_ICXC7Z010_I26_PSDD_1: length 3.5
  TOP w0.102: U511.H3 v2(85.99,23.1)
  BOTTOM w0.102: R634.1 87.74,21.91 86.55,23.1 v2(85.99,23.1)
UNNAMED_41_ICXC7Z010_I26_PSDDRV: length 1.2
  TOP w0.102: U511.J3 v2(87.12,24.23)
  BOTTOM w0.102: R635.1 86.71,23.82 v2(87.12,24.23)
UNNAMED_42_CAP_I17_N1: length 20.4
  TOP w0.305: 82.59,24.79 v2(83.16,24.79)
  L6_SIG w0.305: 78.99,22.55 81.4,24.96 81.81,24.96 82.32,24.46 82.82,24.46 v2(83.16,24.79)
  L6_SIG w0.508: 78.99,22.55 78.8,22.55 77.19,20.94 77.19,20.07 78.94,18.32 78.94,13.27 v1(79.21,13)
  BOTTOM w0.305: v2(83.16,24.79) 82.79,24.42 C688.1
  BOTTOM w0.406: v1(79.21,13) 79.7,12.51 C684.1 79.78,12.43 80.51,11.7 E682.2
UNNAMED_42_CAP_I17_N2: length 24.6
  TOP w0.305: U511.G8 v2(82.59,25.36) U511.F8 ; U511.H7 v2(83.72,26.49) 84.29,26.49 U511.J7
  TOP w0.508: E687.2 79.06,11.75 v1(78.5,12.31)
  L6_SIG w0.305: v2(82.59,25.36) 82.36,25.59 81.36,25.59 79.34,23.57 79.03,23.57
  L6_SIG w0.406: v2(82.59,25.36) v2(83.72,26.49)
  L6_SIG w0.508: 79.03,23.57 78.68,23.57 76.42,21.31 76.42,19.4 78.13,17.69 78.13,12.68 v1(78.5,12.31)
  BOTTOM w0.305: C688.2 82.24,24.88 82.24,25 v2(82.59,25.36)
  BOTTOM w0.406: C684.2 78.58,12.31 v1(78.5,12.31)
UNNAMED_42_DIOLED_I60_N: length 1.3
  TOP w0.102: DS11.C 106.02,21.49 R691.1
UNNAMED_42_DIOLED_I74_N: length 28
  TOP w0.102: DS12.C 106.36,13.11 105.51,12.27 v1(105.51,10.61)
  BOTTOM w0.102: R215.1 85.62,6.12 88.11,3.63 94.84,3.63 98.97,7.76 102.02,7.76 104.11,9.85 104.75,9.85 v1(105.51,10.61)
UNNAMED_42_ICXC7Z010_I13_CFGBVS: length 11.2
  TOP w0.102: U511.F6 v2(83.16,23.66)
  BOTTOM w0.102: R216.2 80.43,16.39 80.87,16.84 80.87,18.55 84.11,21.79 84.11,22.17 83.86,22.42 83.86,22.68 84.11,22.93 84.11,23.24 83.69,23.66 v2(83.16,23.66)
UNNAMED_42_ICXC7Z010_I13_DONE0: length 18.8
  TOP w0.102: U511.M7 v2(86.55,28.19)
  L5_SIG w0.114: v2(86.55,28.19) 86.55,28.74 87.22,29.41 87.22,30.17 89.38,32.33 93.7,32.33 v1(98.97,37.6)
  BOTTOM w0.102: Q512.1 98.97,36.68 v1(98.97,37.6)
UNNAMED_42_ICXC7Z010_I13_INITB0: length 8.4
  TOP w0.102: R689.1 78.54,16.85 80.91,19.22 80.91,20.28 82.59,21.96 U511.D5
UNNAMED_42_ICXC7Z010_I13_PROGRA: length 7.6
  TOP w0.102: U511.K6 v2(85.99,26.49)
  BOTTOM w0.102: v2(85.99,26.49) 85.99,27.03 87.5,28.55 87.5,28.97 87.31,29.16 87.31,29.75 88.75,31.19 89.13,31.19 R685.1
UNNAMED_42_ICXC7Z010_I13_VCCBAT: length 5.2
  TOP w0.102: U511.E6 v2(82.59,23.1)
  BOTTOM w0.102: v2(82.59,23.1) 82.02,23.1 81.6,23.52 81.32,23.52 79.9,22.1 79.52,22.1 R681.2
UNNAMED_42_ICXC7Z010_I13_VP0: length 15.9
  TOP w0.102: U511.G7 v2(83.72,25.36) ; v1(91.92,34.49) R148.2 R213.1
  L6_SIG w0.114: v2(83.72,25.36) 84.3,25.94 84.3,26.49 84.81,27 84.81,28.13 85.03,28.35 89.14,32.46 91.03,32.46 91.92,33.35 v1(91.92,34.49)
UNNAMED_42_RES_I61_N2: length 17.6
  TOP w0.102: v1(103.9,23.1) 104.32,22.68 105.69,22.68 R691.2
  BOTTOM w0.102: Q1.3 96.11,32.2 96.68,31.63 96.68,29.73 97.57,28.84 98.97,28.84 103.35,24.46 103.35,23.65 v1(103.9,23.1)
UNNAMED_42_RES_I73_N2: length 2.4
  BOTTOM w0.102: Q2.3 82.98,6.98 R215.2
UNNAMED_42_TRANNMOSFETV8_I36_D: length 3.8
  BOTTOM w0.102: Q512.3 99.73,34.43 98.84,35.32 98.08,35.32 97.05,36.34 Q1.2
UNNAMED_43_ADP5589V2_I25_RSTN: length 1.4
  TOP w0.102: R87.2 52.82,34.65 U15.17
UNNAMED_45_ADP198_I317_VOUT: length 5
  TOP w0.254: 105.25,45.16 U16.A2 105.63,45.67
  TOP w0.406: C280.1 105.39,44.99 ; C280.1 105.88,44.46 ; C280.1 C281.1 ; C281.1 105.88,43.44 ; C281.1 105.39,42.91
  BOTTOM w0.508: 105.51,43.3 R212.1 105,43.8
  vias: v1(106.14,45.41) v1(106.14,44.71) v1(106.14,44.02) v1(106.14,43.32)
UNNAMED_45_CAP_I416_N1: length 2.7
  TOP w0.635: 99.22,59.99 C312.1 98.28,59.95 ; 103.19,63.83 C313.1 103.23,64.77
UNNAMED_45_CHOKE4P_I331_N2: length 5
  TOP w0.102: 103.35,34.85 100.74,34.85 100.48,34.6 L1.2 ; 103.35,34.85 D739.C ; 103.35,34.85 104,34.85 104.19,34.67 P516.3
UNNAMED_45_CHOKE4P_I331_N3: length 5
  TOP w0.102: L1.3 100.51,35.4 100.79,35.12 102.21,35.12 ; D741.C 102.21,35.12 ; 102.21,35.12 103.98,35.12 104.18,35.32 P516.2
UNNAMED_45_CN5P3SHLD_I255_N6: length 1.1
  TOP w0.508: 107.01,40.03 R744.1 107.54,40.59
UNNAMED_45_CN5P3SHLD_I256_N6: length 1.7
  TOP w0.508: 106.54,58.27 R749.1 ; R749.1 107.1,57.73 ; R749.1 107.66,58.27
UNNAMED_45_LINLTC4415_I406_CL_1: length 1.8
  TOP w0.102: v1(104.11,59.51) 103.72,59.75 U21.5
  BOTTOM w0.102: v1(104.11,59.51) 103.62,60 R192.1
UNNAMED_45_LINLTC4415_I406_CLIM: length 1.8
  TOP w0.102: U21.4 103.36,59.4 v1(103.6,59)
  BOTTOM w0.102: v1(103.6,59) 103.11,59.5 R191.2
USB_ID: length 58
  TOP w0.102: U524.23 59.38,30.95 v1(59.15,30.73) ; P516.4 103.13,34.02 102.84,33.73 v1(101.83,33.73)
  BOTTOM w0.102: v1(101.83,33.73) 101.83,37.03 101.32,37.54 99.67,37.54 99.1,38.11 98.78,38.11 98.4,37.73 93.7,37.73 92.49,38.94 81.95,38.94 80.73,40.15 75.11,40.15 74.59,39.63 74.59,37.86 70.76,34.03 60.98,34.03 60.55,33.6 60.55,31.7 59.58,30.73 v1(59.15,30.73)
USB_OTG_CPEN: length 59.3
  TOP w0.102: U524.17 60.13,35.09 v1(60.62,35.57) ; v1(104.11,47.44) 104.75,46.81 U16.B1
  BOTTOM w0.102: v1(104.11,47.44) 103.29,46.62 103.29,40.78 101.83,39.32 99.6,39.32 99.29,39 98.42,39 98.04,38.62 94.12,38.62 92.86,39.88 82.32,39.88 81.1,41.09 74.78,41.09 73.63,39.95 73.63,38.29 70.29,34.95 68.03,34.95 67.24,35.74 64.72,35.74 64.02,35.04 61.15,35.04 v1(60.62,35.57)
USB_OTG_N: length 48.1
  TOP w0.102: L1.4 97.49,35.4 93.11,39.77 82.45,39.77 81.25,40.97 74.14,40.97 70.65,37.48 60.3,37.48 58.98,36.15 58.98,33.27 59.29,32.95 U524.19
USB_OTG_P: length 48
  TOP w0.102: L1.1 97.86,34.6 97.79,34.67 97.79,35.05 97.7,35.13 97.38,35.13 93,39.51 82.34,39.51 81.14,40.7 74.25,40.7 70.76,37.21 60.41,37.21 59.24,36.04 59.24,35.63 59.33,35.54 59.33,35.33 59.24,35.24 59.24,35.05 59.33,34.96 59.33,34.75 59.24,34.66 59.24,34.45 59.33,34.36 59.33,34.16 59.24,34.07 59.24,33.92 59.33,33.83 59.33,33.63 59.24,33.54 59.24,33.38 59.4,33.22 59.59,33.22 59.82,33.45 U524.18
USB_VBUS_OTG: length 59.9
  TOP w0.254: v1(59.28,31.45) 59.29,31.45 U524.22
  TOP w0.305: 99.54,38.22 99.54,38.68 ; 99.54,38.68 99.95,38.68 ; 99.54,38.68 99.54,39.14 ; R156.1 101.59,39.06 ; R156.1 101.59,38.05 ; R156.1 101.09,38.55
  BOTTOM w0.508: v1(59.28,31.45) 59.54,31.45 60.04,31.95 60.04,33.86 60.78,34.59 64.22,34.59 64.92,35.29 66.99,35.29 67.79,34.49 70.46,34.49 74.14,38.17 74.14,39.82 74.9,40.59 81,40.59 82.14,39.44 92.68,39.44 93.95,38.17 98.21,38.17 98.59,38.55 99.54,38.55 99.67,38.43 99.67,38.42 100.04,38.05 v1(100.3,38.05) v1(100.87,38.05) 101.32,38.05 103.99,40.71 103.99,42.11 104.32,42.44 R212.2
  vias: v1(100.3,38.68) v1(100.87,38.68)
USR_BTN: length 78.7
  TOP w0.102: S1.1 105.81,24.16 105.26,24.71 v1(104.75,24.71) 104.49,24.97 R145.2 ; v1(67.92,15.31) 68.43,14.81 69.44,14.81 70.08,15.44 70.08,16.46 70.58,16.96 71.12,16.96 75.06,20.9 75.88,20.9 78.64,23.66 U511.B9
  L6_SIG w0.114: v1(104.37,10.74) 106.34,12.71 106.34,22.62 104.75,24.2 v1(104.75,24.71)
  BOTTOM w0.102: v1(67.92,15.31) 67.92,13.79 70.2,11.5 73.25,11.5 74.9,9.85 79.09,9.85 80.74,8.2 84.94,8.2 89.19,3.95 94.65,3.95 98.84,8.14 101.76,8.14 v1(104.37,10.74)
USR_LED: length 45.4
  TOP w0.102: U511.D10 v2(79.2,25.36)
  L5_SIG w0.114: v2(79.2,25.36) 78.6,25.36 78.33,25.09 73.89,25.09 69.19,20.39 66.27,20.39 65.63,19.76 65.63,18.36 v1(66.27,17.73)
  BOTTOM w0.102: v1(66.27,17.73) 66.27,16.08 67.41,14.93 67.41,13.54 69.82,11.12 73,11.12 74.65,9.47 78.84,9.47 81.63,6.68 81.63,6.04 82.01,5.66 82.78,5.66 83.72,4.72 Q2.1 84.05,4.22 R214.1
VTT_0P75: length 31.9
  TOP w0.203: U509.3 102.43,29.69 102.61,29.69
  TOP w0.508: 102.9,29.4 102.61,29.69
  TOP w0.635: 103.24,28.25 103.69,28.7 ; 103.24,28.25 103.74,27.76 ; 103.24,28.25 102.75,28.75
  BOTTOM w0.305: R627.2 103.64,17.66 ; R627.2 103.92,16.8 R612.2 104.77,16.53 ; R627.2 103.67,17.05 ; R627.2 103.02,17.7 ; R610.2 103.07,12.25 ; R610.2 R609.2 ; R610.2 103.11,12.86 ; R601.2 101.94,11.12 ; R601.2 R609.2 ; R601.2 R628.2 ; R603.2 100.88,20.28 ; R603.2 R613.2 ; R603.2 100.59,19.99 R619.2 ; 96.49,20.16 R604.2 ; R604.2 97.14,20.81 ; R604.2 96.53,20.78 ; R611.2 104.63,13.81 ; 99.25,14.41 R630.2 R622.2 ; R613.2 99.7,20.88 ; R613.2 100.31,20.85 ; R628.2 101.37,10.55 ; R628.2 R632.2 ; 103.3,19.32 C615.1 ; C615.1 103.33,18.59 ; C615.1 104.05,18.56 ; R620.2 96.08,19.75 ; R620.2 95.47,19.71 ; R620.2 R621.2 ; R608.2 102.01,19.15 ; R608.2 102.04,18.54 ; R608.2 R619.2 ; 94.33,18.58 R606.2 ; R606.2 R631.2 ; R606.2 R621.2 ; R609.2 102.51,11.68 ; R632.2 R624.2 ; R632.2 100.81,9.99 ; R624.2 100.24,9.42 ; R624.2 99.63,9.38 ; R629.2 98.12,15.54 ; 102.72,28.43 R642.1 103.43,28.44 ; R621.2 94.9,19.15 ; R619.2 101.44,19.71 ; R605.2 99.46,21.69 ; R605.2 98.85,21.73 ; R605.2 99.5,21.08 ; R602.2 103.85,16.74 ; R623.2 98.68,14.97
  vias: v1(104.01,27.58) v1(104.55,28.12)
VTTVREF: length 82
  TOP w0.152: 97.39,15.52 v2(96.75,16.16)
  TOP w0.203: U509.6 100.62,32.72 v1(100.94,33.03)
  TOP w0.305: 96.19,16.16 v2(96.75,16.16) ; U646.H1 v2(98.46,9.93) ; U511.F4 v2(84.29,22.53)
  TOP w0.406: 102.97,10.56 102.97,12.01 104.62,13.66
  TOP w0.508: 103.35,19 104.62,17.73 104.62,13.66 ; 103.35,19 104.43,20.08 v1(104.43,21.54) ; 103.35,19 101.57,17.22 101.06,17.22 98.94,15.1 97.81,15.1 97.39,15.52 ; 100.4,7.99 96.6,4.19 92.63,4.19 v1(91.79,5.03) ; 100.4,7.99 102.97,10.56 ; 100.4,7.99 v2(98.46,9.93)
  BOTTOM w0.152: 85.44,21.39 85.44,21.96 85,22.39 84.43,22.39 84.43,21.83 84.87,21.39 85.44,21.39
  BOTTOM w0.305: C650.2 98.11,9.59 v2(98.46,9.93) ; C692.2 85.5,19.06 ; v1(100.94,33.03) 100.49,32.59 100.49,32.08 C660.1 101.2,31.37 C657.1 ; v2(96.75,16.16) 96.07,16.16 C654.1
  BOTTOM w0.406: v2(84.29,22.53) 84.43,22.39
  BOTTOM w0.508: C657.1 101.7,30.92 101.7,30.49 ; v1(91.79,5.03) 91.03,5.03 82.52,13.54 82.52,16.52 83.16,17.16 83.6,17.16 86.07,19.63 86.07,20.47 85.44,21.11 85.44,21.39
  BOTTOM w0.635: 101.7,30.49 101.45,30.24 101.45,28.59 101.83,28.2 101.83,27.12 103.92,25.03 103.92,24.14 104.68,23.38 104.68,21.79 v1(104.43,21.54)
VTUNE: length 3.7
  TOP w0.305: R86.2 68.36,63.57 C239.1 66.63,61.85 U14.7

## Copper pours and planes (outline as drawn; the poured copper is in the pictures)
1.35V on TOP: 92.3,40.59 92.3,42.24 91.92,42.62 91.92,46.43 89.51,46.43 89.51,43 89.38,42.87 89.38,40.59
1.35V on BOTTOM: 89.38,42.87 89.38,40.65 92.68,40.65 92.68,42.36 93.06,42.75 93.06,44.52 89.51,44.52 89.51,43
1V0_D on TOP: 84.55,47.32 84.55,45.29 85.19,44.65 89.13,44.65 89.13,45.54 87.35,47.32
1V0_D on BOTTOM: 85.19,47.32 85.19,44.65 89.13,44.65 89.13,45.67 88.36,46.43 88.36,47.32
1V8_A_1 on BOTTOM: 55.73,48.71 55.73,42.36 56.68,42.36 57.82,43.51 57.82,48.71
1V8_A_2 on TOP: 67.79,53.16 67.79,52.91 68.24,52.46 69.31,52.46 69.31,53.92 68.55,53.92
1V8_A_2 on BOTTOM: 68.04,51.13 68.04,54.68 70.39,54.68 70.39,52.14 69.7,52.14 69.7,51.13
1V8_D on TOP: 69.59,49.63 68.73,49.63 68.38,49.98 68.38,50.42 68.88,50.92 69.59,50.92
1V8_D on TOP: 100.9,27.17 99.42,28.65 100.46,29.69 101.94,28.21
1V8_D on BOTTOM: 70.14,22.63 71.33,23.82 72.24,23.82 76.18,19.87 74.54,18.23
1V8_D on BOTTOM: 98.65,41.6 98.65,39.7 96.37,39.7 96.37,44.52 98.02,44.52 98.02,42.24
1V8_D on BOTTOM: 68.35,35.57 68.35,36.27 67.78,36.84 57,36.84 55.6,38.24 55.6,41.86 57.12,41.86 57.12,39.89 58.08,38.94 59.6,38.94 59.6,38.36 60.93,38.36 60.93,38.94 61.06,38.94 61.69,39.57 68.04,39.57 70.39,41.92 70.39,46.43 71.6,47.64 71.6,51.7 71.09,52.21 71.09,53.41 72.74,53.41 72.93,53.22 72.93,38.49 70.01,35.57
1V8_D on L8_PWR: 104.08,4.29 85.41,2.07 66.65,0.87 66.65,7.25 65.38,8.52 65.38,17.41 59.03,23.76 59.03,30.3 60.93,30.3 60.93,36.65 69.31,36.65 76.55,29.41 76.78,29.41 78.18,28.01 78.18,27.32 79.79,25.7 82.9,28.81 84.3,27.42 84.49,27.42 85.25,28.18 86.91,26.52 78.62,18.23 78.58,18.23 78.4,18.05 78.4,14.29 80.17,12.52 87.1,12.52 93.95,19.37 93.95,41.54 93.77,41.73 84.56,41.73 81.07,45.22 70.14,45.22 70.14,50.18 66.97,50.18 66.97,54.11 72.68,54.11 72.68,50.94 82.21,50.94 82.21,48.08 102.53,48.08 102.53,40.27 101.57,39.32 101.57,36.01 104.3,36.01 104.3,34.24 102.08,34.24 102.08,32.33 105.06,29.35 108.5,29.35 108.5,19.37 108.5,8.61 107.49,5.87 104.95,4.43
1V35 on TOP: 88.26,19.41 89.82,17.85 87.99,16.02 86.43,17.58
1V35 on BOTTOM: 86.46,17.6 87.98,16.08 89.76,17.85 88.24,19.38
1V35 on BOTTOM: 93.44,40.21 93.44,42.49 94.08,43.13 94.08,44.52 95.48,44.52 95.48,43.63 95.6,43.63 95.86,43.38 95.86,39.57 94.08,39.57
1V35 on L3_PWR: 104.08,4.29 91.11,2.64 78.08,1.48 78.08,22.68 84.88,22.68 89.19,26.99 89.19,30.8 92.37,33.98 92.37,46.17 102.53,46.17 102.53,40.27 101.57,39.32 101.57,36.01 104.3,36.01 104.3,34.24 102.08,34.24 102.08,32.33 105.06,29.35 108.5,29.35 108.5,26.99 108.5,8.61 107.49,5.87 104.95,4.43
3V3_A on TOP (solid shape): 18.51,6.84 18.06,6.84 17.91,6.78 17.85,6.64 17.85,6.31 17.75,6.31 17.65,6.31 17.65,6.64 17.59,6.78 17.45,6.84 17.04,6.84 16.9,6.78 16.84,6.64 16.84,6.31 16.79,6.31 16.74,6.31 16.68,6.3 16.54,6.3 16.52,6.32 16.49,6.35 16.49,6.77 16.43,6.91 16.29,6.97 15.77,6.97 15.74,6.99 15.72,7.02 15.72,7.57 18.51,7.57
3V3_A on BOTTOM (solid shape): 18.9,6.42 18.62,6.42 18.62,6.85 18.56,6.99 18.41,7.05 17.85,7.05 17.77,7.03 17.7,6.98 17.63,6.95 17.55,6.98 17.48,7.03 17.4,7.05 16.84,7.05 16.69,6.99 16.63,6.85 16.63,6.42 16.36,6.42 16.36,7.57 18.9,7.57
3V3_A on TOP: 29.44,15.95 29.44,19.25 28.04,19.25 28.04,15.95
3V3_A on BOTTOM: 55.85,57.48 55.85,54.56 57.88,54.56 57.88,55.95 58.14,56.21 58.14,57.48
3V3_A on BOTTOM: 38.33,22.43 38.33,20.77 41.25,20.77 42.01,21.54 42.9,21.54 42.9,22.81 40.23,22.81 39.85,22.43
3V3_A on BOTTOM: 41.63,38.55 41.63,35.89 43.15,35.89 43.15,37.41 42.52,38.05 42.52,38.55
3V3_A on BOTTOM: 35.66,23.57 31.21,23.57 31.21,21.54 32.29,21.54 32.68,21.92 35.66,21.92
3V3_A on L3_PWR: 16.48,6.49 16.48,27.12 34.26,27.12 34.26,39.19 45.06,39.19 45.06,56.02 57.12,56.02 57.12,20.14 38.14,20.14 38.14,6.49
3V3_A_1 on BOTTOM: 58.39,55.19 58.39,54.18 56.61,54.18 56.61,51.13 57.88,51.13 57.88,51.76 65.89,51.76 65.89,55.19
3V3_CLK_A on BOTTOM: 57.38,58.11 59.92,58.11 60.04,57.99 61.95,57.99 61.95,59.38 57.38,59.38
3V3_CLK_A on L5_SIG: 65.38,56.02 62.52,56.02 59.98,58.56 59.98,66.49 72.05,66.49 72.05,58.37 70.78,57.1 66.46,57.1
3V3_D on TOP: 78.33,37.16 75.54,37.16 75.54,39.44 78.33,39.44
3V3_D on BOTTOM: 75.54,36.83 78.43,36.83 78.43,39.52 75.54,39.52
3V3_D on BOTTOM: 80.49,43.13 77.7,43.13 77.7,47.44 80.49,47.44
3V3_D on L8_PWR: 57.76,2.99 57.76,15.51 51.86,21.41 32.68,21.41 32.68,15.31 21.69,15.31 21.69,26.55 28.55,26.55 28.55,34.11 39.98,34.11 39.98,27.12 49.5,27.12 49.5,45.54 66.97,45.54 66.97,49.54 69.51,49.54 69.51,44.59 80.8,44.59 84.3,41.09 93.32,41.09 93.32,19.64 86.84,13.15 80.43,13.15 79.03,14.56 79.03,18.05 78.95,18.13 87.25,26.43 87.25,26.62 85.38,28.48 85.13,28.48 84.4,27.75 82.9,29.25 79.79,26.13 78.48,27.44 78.48,28.14 77,29.63 77,29.86 69.57,37.28 60.3,37.28 60.3,30.93 58.39,30.93 58.39,23.5 64.74,17.15 64.74,8.26 66.01,6.99 66.01,2.99
3V3_D_LA on L6_SIG: 0.73,34.74 0.73,13.92 8.74,13.92 9.24,14.42 10.01,14.42 11.91,16.33 11.91,34.74
3V3_SC_A on TOP: 40.61,43.63 40.61,40.84 40.36,40.59 40.36,39.32 40.74,38.94 45.44,38.94 45.44,41.73 44.3,41.73 44.3,40.08 43.03,40.08 41.5,41.6 41.5,42.49 43.41,42.49 43.41,43.63 ; 1 cut-out
3V3_SC_A on TOP: 40.64,55.57 40.64,50.37 42.64,50.37 42.64,50.8 45.31,50.8 45.31,53.67 44.3,53.67 44.3,52.02 43.41,52.02 41.5,53.92 41.5,54.43 43.41,54.43 43.41,55.57 ; 1 cut-out
3V3_SC_A on BOTTOM: 41.25,38.94 42.52,38.94 42.52,40.84 40.74,40.84 40.74,39.44
3V3_SC_A on L3_PWR: 39.34,39.82 39.34,56.02 44.42,56.02 44.42,39.82
4V0_A on TOP: 31.47,57.99 33.5,57.99 33.5,60.02 31.47,60.02
4V0_A on TOP: 30.14,48.46 30.14,47.89 30.2,47.83 30.2,47.19 33.55,47.19 33.55,48.28 33.37,48.46
4V0_A on TOP: 32.36,61.16 30.96,61.16 30.96,63.57 32.48,63.57 32.48,62.56 32.36,62.43
4V0_A on BOTTOM: 32.42,61.16 30.96,61.16 30.96,62.43 32.42,62.43
4V0_A on L5_SIG: 29.82,46.81 33.63,46.81 34.9,48.08 34.9,51.89 36.17,53.16 36.17,63.32 30.96,63.32 30.96,50.62 32.99,50.62 32.99,49.98 29.82,49.98
5V0_A on TOP: 83.41,62.68 85.44,62.68 86.08,62.05 86.08,59.51 83.41,59.51
5V0_A on TOP: 34.39,63.45 34.39,62.3 38.07,62.3 38.07,63.45
5V0_A on TOP: 43.66,1.72 47.34,1.72 47.34,3.5 46.2,3.5 46.2,4.26 46.07,4.39 45.06,4.39 45.06,5.53 43.66,5.53
5V0_A on TOP: 54.2,17.22 54.2,15.82 51.92,15.82 51.53,16.2 50.01,16.2 50.01,17.98 53.44,17.98 53.44,17.47 53.69,17.22
5V0_A on TOP: 36.99,14.22 39.47,14.22 39.47,15.31 40.23,16.08 40.23,18.11 37.31,18.11 37.31,16.08 36.99,15.76
5V0_A on BOTTOM: 37.56,15.69 40.23,15.69 40.23,18.36 37.56,18.36
5V0_A on L3_PWR: 38.77,1.41 38.77,19.5 57.76,19.5 57.76,56.47 57.57,56.65 34.58,56.65 34.58,64.59 48.48,64.59 48.48,63.06 48.5,62.69 48.55,62.33 48.55,62.05 48.62,62.05 52.28,59.26 55.94,62.05 86.33,62.05 86.33,46.81 71.09,46.81 71.09,10.3 50.64,10.3 47.6,7.25 47.6,1.41
6V0_A on TOP: 40.74,13.54 46.33,13.54 46.33,15.82 40.74,15.82
6V0_A on TOP: 20.42,11.12 22.01,11.12 22.01,13.6 20.42,13.6
6V0_A on BOTTOM: 42.26,13.66 46.71,13.66 46.71,15.95 42.26,15.95
6V0_A on BOTTOM: 27.79,24.2 27.79,22.68 29.56,22.68 29.56,24.2
6V0_A on L5_SIG: 21.18,10.93 32.36,10.93 35.34,13.92 45.82,13.92 45.82,20.77 34.58,20.77 34.58,23.31 27.6,23.31 27.6,22.36 26.64,21.41 26.01,21.41 26.01,14.68 25.44,14.11 22.26,14.11 21.18,13.03
6V0_AWG_A on BOTTOM: 27.28,24.2 27.28,22.68 25.75,22.68 25.75,24.2
6V0_AWG_A on L5_SIG: 22.32,22.68 22.32,33.47 29.82,33.47 29.82,26.93 29.31,26.93 29.25,26.87 29.25,26.36 29.06,26.17 28.67,26.17 28.04,25.54 25.5,25.54 25.5,25.41 25.69,25.22 26.07,25.22 26.71,24.58 26.39,24.58 26.39,22.68
6V0_SC_A on BOTTOM: 37.31,37.16 38.2,37.16 38.64,36.71 40.49,36.71 40.49,38.17 39.09,38.17 38.45,37.54 37.31,37.54
6V0_SC_A on BOTTOM: 32.74,60.14 34.14,60.14 34.14,61.8 32.74,61.8
6V0_SC_A on BOTTOM: 38.83,46.05 39.34,46.05 39.34,46.75 39.85,47.25 40.23,47.25 40.3,47.32 40.3,49.35 38.14,49.35 38.14,48.91 38.83,48.91
6V0_SC_A on L8_PWR: 40.61,27.76 40.61,34.74 28.55,34.74 28.55,41.73 21.56,41.73 21.56,60.78 39.98,60.78 39.98,40.46 48.87,40.46 48.87,27.76
6V0_USR_A on TOP (solid shape): 19.25,12.74 19.31,12.59 19.45,12.53 19.98,12.53 19.98,12.01 18.83,12.01 18.77,12.02 18.72,12.02 18.67,12.02 18.67,12.35 18.61,12.5 18.46,12.56 18.06,12.56 17.91,12.5 17.85,12.35 17.85,12.02 17.75,12.02 17.65,12.02 17.65,12.35 17.59,12.5 17.45,12.56 17.04,12.56 16.9,12.5 16.84,12.35 16.84,12.02 16.79,12.02 16.74,12.02 16.68,12.01 16.54,12.01 16.52,12.04 16.49,12.06 16.49,12.48 16.43,12.63 16.29,12.69 15.77,12.69 15.74,12.7 15.72,12.74 15.72,13.47 19.25,13.47
6V0_USR_A on BOTTOM (solid shape): 18.9,12.81 18.87,12.73 18.79,12.7 18.24,12.7 18.09,12.64 18.03,12.5 18.03,12.01 17.6,12.01 17.6,12.5 17.54,12.64 17.4,12.7 16.84,12.7 16.69,12.64 16.63,12.5 16.63,12.23 16.57,12.14 16.46,12.16 16.36,12.27 16.36,12.9 16.74,13.28 18.9,13.28
-3V3_A on TOP (solid shape): 13.59,11.98 13.63,11.91 13.68,11.85 13.68,11.41 13.6,11.31 13.58,11.18 13.58,11.12 13.49,11.12 13.44,11.13 13.38,11.14 13.33,11.14 13.33,11.47 13.27,11.61 13.13,11.67 12.72,11.67 12.58,11.61 12.52,11.47 12.52,11.14 12.42,11.13 12.32,11.14 12.32,11.47 12.26,11.61 12.11,11.67 11.66,11.67 11.66,12.14 13.44,12.14
-3V3_A on BOTTOM (solid shape): 13.94,11 13.16,11 13.16,11.42 13.1,11.57 12.95,11.62 12.39,11.62 12.25,11.56 12.19,11.42 12.19,11 11.63,11 11.63,11.42 11.57,11.57 11.43,11.62 10.87,11.62 10.8,11.65 10.77,11.73 10.77,12.27 13.94,12.27
-3V3_A on TOP: 46.71,38.81 46.71,37.41 49.12,37.41 49.12,38.81
-3V3_A on TOP: 40.87,19 40.87,21.03 38.71,21.03 38.45,20.77 38.45,19
-3V3_AWG_A on TOP: 41.25,22.93 41.25,24.46 41.31,24.52 41.31,25.79 41.06,26.05 41.06,27.95 39.15,27.95 39.09,27.89 39.09,25.73 39.15,25.66 40.3,25.66 40.3,22.93
-3V3_SC_A on TOP: 44.42,56.72 45.18,56.72 45.18,58.11 47.09,58.11 47.09,59.64 44.42,59.64
-3V3_SC_A on TOP: 47.72,39.19 47.72,42.62 47.5,42.85 47.5,43.51 47.37,43.51 47.37,42.87 46.33,42.87 46.33,43.63 48.99,43.63 48.99,39.19
-3V3_SC_A on TOP: 44.3,44.78 45.18,44.78 45.18,46.17 45.57,46.17 45.95,46.56 47.34,46.56 47.34,47.83 44.3,47.83
-3V3_SC_A on TOP: 46.96,51.38 46.96,52.52 47.72,53.29 47.72,54.56 47.5,54.79 47.5,55.45 47.37,55.45 47.37,54.81 46.33,54.81 46.33,55.57 48.99,55.57 48.99,51.38
-3V3_SC_A on BOTTOM: 44.55,60.27 44.55,58.62 47.09,58.62 47.09,60.27
-3V3_SC_A on BOTTOM: 44.68,48.33 44.68,46.56 47.22,46.56 47.22,48.33
-3V3_SC_A on L8_PWR: 40.61,41.09 40.61,60.78 44.93,60.78 48.87,56.84 48.87,41.09
-5V0_SC_A on TOP: 36.78,52.65 36.78,53.57 37.56,53.57 37.56,54.3 37.44,54.43 37.44,55.7 37.95,55.7 38.2,55.45 38.96,55.45 38.96,55.19 38.58,54.81 38.58,52.91 38.33,52.65
-5V0_SC_A on TOP: 15.85,50.87 14.07,50.87 14.07,52.65 15.47,52.65 15.85,52.27
-5V0_SC_A on TOP: 36.8,40.84 38.58,40.84 38.58,43.76 37.44,43.76 37.44,42.62 37.56,42.49 37.56,41.86 36.8,41.86
-5V0_SC_A on BOTTOM: 15.72,50.11 14.32,50.11 13.94,50.49 13.94,53.16 15.72,53.16
-5V0_SC_A on L3_PWR: 34.26,39.82 34.26,48.71 29.18,48.71 29.18,55.38 22.2,55.38 22.2,50.94 13.94,50.94 13.94,59.51 33.95,59.51 33.95,56.02 38.71,56.02 38.71,39.82
